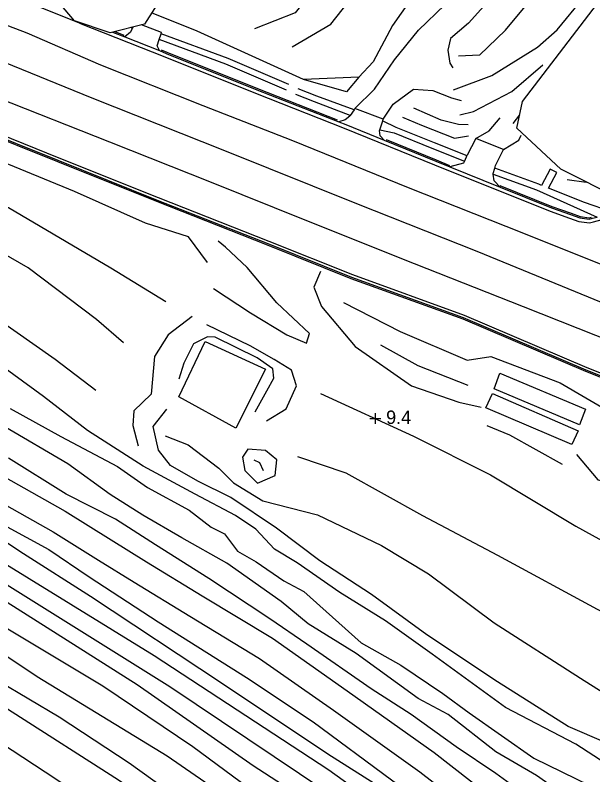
# Model space of a CAD drawing. Extents: x 2316231 to 2323598, y 363169 to 371906.
# Drawn here: x 2320501.8 to 2320716.5, y 365899 to 366181.3 of the extents above; entities that cross this region are included whole.
import ezdxf

# ---------------------------------------------------------------- set-up
doc = ezdxf.new("R2010")
doc.units = 0
for name, color, linetype in [('RD_DTM_BkLn1', 7, 'Continuous'), ('RD_DTM_Holes', 7, 'Continuous'), ('RD_DTM_Void', 7, 'Continuous'), ('RD_EX_H2O', 7, 'Continuous'), ('RD_EX_Road', 7, 'Continuous')]:
    doc.layers.add(name, color=color, linetype=linetype)

msp = doc.modelspace()

# ---------------------------------------------------------------- linework, layer by layer
at = {"layer": 'RD_DTM_BkLn1'}
for p, q in [((2320629.575, 366158.256), (2320608.931, 366157.378)), ((2320689.326, 366144.194), (2320686.807, 366141.06)), ((2320706.982, 366120.247), (2320714.138, 366119.274))]:
    msp.add_line(p, q, dxfattribs=at)
for points in [[(2320533.6, 366162.638), (2320506.3, 366174.535), (2320465.853, 366190.084), (2320436.355, 366201.486), (2320415.415, 366210.263), (2320393.459, 366218.872), (2320360.843, 366231.403), (2320327.669, 366244.242), (2320294.269, 366258.238), (2320257.317, 366273.156), (2320231.348, 366282.823)], [(2320577.045, 366272.997), (2320581.683, 366268.882), (2320590.588, 366269.346), (2320603.735, 366274.18), (2320622.56, 366276.839), (2320630.763, 366265.105), (2320644.145, 366234.528), (2320652.277, 366208.945), (2320650.853, 366190.101), (2320642.133, 366177.456), (2320634.842, 366163.914), (2320629.575, 366158.256)], [(2320519.241, 366194.477), (2320517.839, 366195.025), (2320508.812, 366198.914), (2320511.466, 366211.647), (2320513.766, 366225.597), (2320524.093, 366232.701), (2320536.386, 366233.795), (2320560.592, 366247.081), (2320573.262, 366252.151), (2320604.622, 366257.303), (2320620.601, 366248.036), (2320623.573, 366223.725), (2320619.71, 366199.683), (2320605.893, 366182.184), (2320590.826, 366176.244)], [(2320684.118, 366175.719), (2320698.663, 366193.461), (2320705.301, 366220.646), (2320700.697, 366236.714)], [(2320703.263, 366175.789), (2320713.115, 366187.867), (2320715.921, 366209.139), (2320713.631, 366228.767)], [(2320604.733, 366169.498), (2320619.153, 366177.986), (2320629.474, 366191.076), (2320638.22, 366215.983)], [(2320670.36, 366178.243), (2320687.373, 366197.435), (2320689.378, 366210.814), (2320686.67, 366215.628)], [(2320608.931, 366157.378), (2320569.481, 366175.328), (2320552.531, 366182.119)], [(2320664.793, 366153.588), (2320679.052, 366158.907), (2320695.928, 366169.428), (2320703.263, 366175.789)], [(2320684.118, 366175.719), (2320674.371, 366166.422), (2320666.555, 366166.07)], [(2321058.006, 365893.08), (2321033.886, 365912.075), (2321009.778, 365931.141), (2320983.8, 365949.981), (2320952.381, 365971.253), (2320929.192, 365985.285), (2320903.037, 365999.401), (2320870.781, 366015.093), (2320839.103, 366027.859), (2320803.486, 366042.258), (2320766.516, 366057.135), (2320724.624, 366072.486), (2320673.583, 366093.446), (2320628.837, 366111.148), (2320579.72, 366130.879), (2320530.352, 366150.424), (2320494.149, 366165.157)], [(2321069.926, 365902.304), (2321045.935, 365921.214), (2321024.91, 365937.287), (2321006.228, 365951.677), (2320983.871, 365968.062), (2320962.43, 365982.06), (2320941.958, 365993.151), (2320911.963, 366009.193), (2320883.216, 366022.963), (2320847.464, 366037.895), (2320813.645, 366051.48), (2320761.655, 366072.109), (2320728.302, 366085.144), (2320690.226, 366100.377), (2320648.068, 366117.161), (2320605.031, 366134.547), (2320571.655, 366147.595), (2320533.6, 366162.638)], [(2320667.112, 366144.247), (2320672.185, 366145.508), (2320686.411, 366152.954), (2320697.926, 366162.797)], [(2320573.321, 366089.418), (2320566.172, 366098.949), (2320550.209, 366103.969), (2320523.872, 366115.782), (2320485.436, 366131.516), (2320459.833, 366142.458), (2320423.52, 366157.007)], [(2320629.575, 366158.256), (2320624.981, 366152.783), (2320608.931, 366157.378)], [(2320557.741, 366074.745), (2320537.357, 366087.276), (2320499.275, 366109.706), (2320450.502, 366132.41), (2320411.79, 366155.498)], [(2320531.807, 366041.883), (2320516.681, 366053.392), (2320478.743, 366079.814), (2320453.669, 366097.202), (2320427.237, 366118.435), (2320403.359, 366133.196), (2320387.968, 366137.594), (2320361.237, 366152.852)], [(2320183.14, 366148.693), (2320239.09, 366117.639), (2320296.494, 366085.739), (2320349.802, 366055.132), (2320405.378, 366025.418), (2320448.083, 365999.362), (2320490.768, 365974.618), (2320559.324, 365931.873), (2320617.279, 365892.959), (2320678.148, 365848.809), (2320727.47, 365811.314), (2320779.04, 365769.194), (2320836.996, 365719.869), (2320889.686, 365671.382)], [(2321107.857, 365825.845), (2321089.033, 365845.956), (2321064.914, 365868.827), (2321040.152, 365890.43), (2321013.859, 365911.449), (2320983.706, 365933.792), (2320958.395, 365951.148), (2320936.89, 365964.698), (2320914.976, 365977.721), (2320890.131, 365990.721), (2320868.682, 366001.198), (2320834.466, 366016.123), (2320800.88, 366029.386), (2320770.06, 366041.822), (2320731.461, 366056.849), (2320690.819, 366072.905), (2320650.247, 366088.926), (2320609.558, 366105.101), (2320574.835, 366119.134), (2320536.92, 366134.034), (2320494.89, 366150.627)], [(2320125.425, 366145.994), (2320161.294, 366129.015), (2320184.806, 366118.194), (2320219.268, 366097.334), (2320257.75, 366078.61), (2320301.401, 366053.593), (2320339.6, 366032.049), (2320388.854, 366006.136), (2320433.491, 365980.54), (2320471.094, 365961.437), (2320509.936, 365935.57), (2320558.33, 365906.04), (2320596.656, 365879.53), (2320637.36, 365850.344), (2320679.307, 365816.521), (2320703.841, 365798.525), (2320711.978, 365788.521), (2320716.795, 365779.622), (2320731.36, 365769.609), (2320746.226, 365761.92), (2320773.664, 365741.714), (2320802.121, 365716.946), (2320848.849, 365676.056), (2320875.469, 365654.227)], [(2320542.082, 366059.505), (2320531.991, 366068.175), (2320506.632, 366087.35), (2320470.997, 366107.883), (2320446.3, 366121.378), (2320401.38, 366146.067)], [(2320670.174, 366140.558), (2320666.583, 366140.697), (2320660.21, 366142.3), (2320649.948, 366146.765)], [(2320182.737, 366143.817), (2320231.045, 366116.001), (2320278.866, 366087.979), (2320328.405, 366059.321), (2320373.611, 366034.853), (2320417.281, 366010.392), (2320460.243, 365986.01), (2320498.805, 365963.232), (2320547.113, 365932.568), (2320590.276, 365902.488), (2320625.131, 365879.992), (2320670.35, 365847.996), (2320704.214, 365820.962), (2320721.604, 365807.145), (2320731.665, 365799.894), (2320745.055, 365790.38), (2320759.08, 365777.797), (2320794.333, 365748.347), (2320828.782, 365718.919), (2320859.537, 365690.73), (2320885.477, 365666.303)], [(2320645.769, 366143.342), (2320652.812, 366140.43), (2320665.172, 366135.574), (2320670.289, 366136.491)], [(2320232.419, 366129.527), (2320276.765, 366104.361), (2320326.97, 366076.072), (2320377.845, 366047.504), (2320438.873, 366013.35), (2320491.432, 365981.475), (2320553.439, 365943.338), (2320618.359, 365900.899), (2320682.218, 365854.928), (2320740.085, 365810.827), (2320800.745, 365760.357), (2320857.803, 365711.976), (2320894.516, 365677.21)], [(2320320.221, 366098.87), (2320343.73, 366084.834), (2320356.505, 366077.219), (2320384.555, 366059.676), (2320419.447, 366040.181), (2320447.866, 366021.901), (2320471.868, 366008.615), (2320488.936, 365996.515), (2320514.303, 365982.74), (2320529.316, 365972.626), (2320554.954, 365955.917), (2320587.739, 365935.149), (2320612.576, 365918.662), (2320641.664, 365897.147), (2320678.381, 365870.456), (2320716.77, 365840.459), (2320734.571, 365828.326), (2320756.632, 365810.066), (2320790.938, 365779.493), (2320809.818, 365763.92), (2320848.173, 365729.232), (2320863.138, 365716.2), (2320899.36, 365685.757), (2320900.62, 365684.576)], [(2320315.308, 366088.614), (2320345.863, 366070.993), (2320387.782, 366047.357), (2320430.265, 366024.388), (2320470.415, 366003.883), (2320504.878, 365981.214), (2320529.854, 365965.458), (2320578.485, 365933.231), (2320618.03, 365906.824), (2320639.032, 365893.635), (2320675.308, 365866.642), (2320706.175, 365841.844), (2320753.882, 365805.574), (2320792.936, 365773.891), (2320828.235, 365743.377), (2320879.989, 365695.168), (2320896.418, 365679.505)], [(2320623.799, 366074.563), (2320644.902, 366063.772), (2320669.823, 366053.098), (2320678.655, 366054.407), (2320704.426, 366044.656), (2320723.457, 366033.572), (2320735.647, 366023.576), (2320753.929, 366012.205), (2320762.157, 366006.679), (2320763.27, 365997.376), (2320762.504, 365991.761), (2320773.429, 365985.539)], [(2320567.611, 366069.257), (2320558.724, 366062.537), (2320553.578, 366054.494), (2320552.293, 366040.517), (2320545.965, 366034.321), (2320545.565, 366028.76), (2320547.505, 366021.302)], [(2320591.032, 366033.915), (2320595.371, 366041.673), (2320597.971, 366046.403), (2320597.553, 366049.906), (2320591.766, 366053.949), (2320576.132, 366061.623), (2320573.332, 366061.753), (2320568.077, 366059.218), (2320564.537, 366051.982), (2320562.691, 366046.061)], [(2320768.392, 365866.361), (2320756.708, 365877.083), (2320744.252, 365887.566), (2320740.687, 365890.766), (2320726.055, 365900.142), (2320710.288, 365910.418), (2320684.057, 365924.05), (2320656.815, 365943.875), (2320639.525, 365956.203), (2320622.508, 365966.719), (2320606.645, 365977.824), (2320598.246, 365982.88), (2320591.282, 365990.258), (2320583.747, 365995.374), (2320568.719, 366003.277), (2320549.326, 366013.752), (2320528.668, 366027.008), (2320512.279, 366039.596), (2320486.864, 366058.051)], [(2320670.261, 366043.662), (2320651.645, 366051.043), (2320637.676, 366058.638)], [(2320615.366, 366040.68), (2320649.844, 366024.913), (2320678.476, 366010.483), (2320710.266, 365991.463), (2320738.082, 365976.027), (2320772.798, 365958.579), (2320790.365, 365945.728)], [(2320499.898, 366035.117), (2320518.783, 366024.708), (2320539.775, 366013.575), (2320551, 366005.825), (2320566.423, 365997.349), (2320574.595, 365991.103), (2320579.668, 365988.57), (2320584.457, 365982.129), (2320591.38, 365978.131), (2320601.704, 365971.102), (2320609.064, 365967.122), (2320630.418, 365948.02), (2320645.146, 365939.719), (2320660.769, 365929.255), (2320670.56, 365922.043), (2320694.612, 365905.223), (2320715.486, 365895.037), (2320733.213, 365880.79), (2320746.065, 365874.627), (2320761.94, 365859.741), (2320768.707, 365850.734), (2320770.054, 365844.1)], [(2320764.035, 365845.663), (2320752.506, 365853.724), (2320736.562, 365865.941), (2320722.342, 365878.987), (2320705.589, 365891.721), (2320695.572, 365898.724), (2320680.484, 365907.597), (2320662.741, 365921.455), (2320651.647, 365927.407), (2320628.585, 365944.084), (2320610.724, 365955.154), (2320600.628, 365963.434), (2320580.454, 365977.629), (2320563.696, 365987.078), (2320549.277, 365995.494), (2320537.141, 366003.22), (2320521.388, 366014.595), (2320497.7, 366028.456)], [(2320677.167, 366028.804), (2320685.55, 366025.332), (2320705.186, 366014.441)], [(2320557.596, 366025.006), (2320566.158, 366021.65), (2320577.537, 366013.023), (2320583, 366007.52), (2320593.883, 366000.802), (2320614.146, 365995.646), (2320637.946, 365984.183), (2320655.496, 365973.743), (2320679.838, 365955.502), (2320712.01, 365934.894), (2320739.613, 365917.475), (2320762.81, 365900.264)], [(2320778.851, 365827.229), (2320776.707, 365828.796), (2320760.961, 365838.918), (2320748.976, 365847.328), (2320737.491, 365856.96), (2320731.391, 365861.609), (2320718.843, 365870.309), (2320708.251, 365878.642), (2320699.269, 365885.241), (2320691.419, 365891.649), (2320680.432, 365899.55), (2320665.759, 365909.434), (2320648.973, 365921.401), (2320634.153, 365930.933), (2320610.18, 365947.515), (2320596.411, 365956.939), (2320573.742, 365971.933), (2320553.973, 365984.422), (2320539.048, 365994.014), (2320520.799, 366003.328), (2320499.315, 366016.701)], [(2320590.504, 366016.077), (2320592.571, 366015.035), (2320594.047, 366012.121)], [(2320606.697, 366017.247), (2320624.739, 366011.232), (2320653.282, 365995.385), (2320681.071, 365980.599), (2320718.12, 365960.616), (2320755.163, 365941.178), (2320778.753, 365919.388)], [(2320543.695, 365879.161), (2320517.247, 365897.216), (2320496.287, 365910.936), (2320471.832, 365924.913)]]:
    msp.add_lwpolyline(points, dxfattribs=at)
at = {"layer": 'RD_DTM_Holes'}
for points in [[(2320743.184, 366208.848), (2320746.914, 366221.959), (2320763.81, 366237.757), (2320780.684, 366241.725), (2320800.176, 366254.868), (2320811.003, 366246.359), (2320800.733, 366223.679), (2320777.231, 366171.911), (2320759.986, 366170.011), (2320738.35, 366162.342), (2320738.441, 366149.94), (2320744.083, 366125.412), (2320726.638, 366113.037), (2320704.663, 366124.002), (2320688.271, 366139.316), (2320690.415, 366149.23), (2320722.742, 366191.581), (2320740.581, 366196.767), (2320743.184, 366208.848)], [(2320516.901, 366187.518), (2320522.26, 366203.453), (2320535.193, 366209.525), (2320546.861, 366206.283), (2320557.353, 366189.738), (2320549.875, 366177.924), (2320537.102, 366174.768), (2320523.785, 366179.153), (2320516.901, 366187.518)]]:
    msp.add_lwpolyline(points, dxfattribs=at)
at = {"layer": 'RD_DTM_Void'}
for p, q in [((2320635.704, 366029.379), (2320635.704, 366033.379)), ((2320633.704, 366031.379), (2320637.704, 366031.379))]:
    msp.add_line(p, q, dxfattribs=at)
at = {"layer": 'RD_EX_H2O'}
msp.add_lwpolyline([(2320221.567, 366109.612), (2320246.01, 366095.432), (2320275.628, 366082.36), (2320308.416, 366062.762), (2320348.828, 366042.465), (2320390.844, 366019.006), (2320428.93, 365996.954), (2320463.386, 365976.566), (2320497.874, 365954.051), (2320534.331, 365932.126), (2320567.896, 365909.551), (2320591.597, 365891.98), (2320624.103, 365868.768), (2320651.363, 365847.548), (2320681.527, 365825.11), (2320715.721, 365799.88), (2320721.819, 365795.078), (2320726.404, 365790.317)], dxfattribs=at)
at = {"layer": 'RD_EX_Road'}
for p, q in [((2320545.345, 366176.462), (2320544.827, 366176.677)), ((2320545.51, 366176.845), (2320545.345, 366176.462)), ((2320537.941, 366174.975), (2320542.521, 366173.17)), ((2320538.779, 366175.182), (2320542.179, 366173.843)), ((2320555.346, 366172.242), (2320556.058, 366174.386)), ((2320542.521, 366173.17), (2320555.402, 366168.094)), ((2320627.798, 366146.159), (2320626.335, 366143.959)), ((2320628.059, 366146.552), (2320627.798, 366146.159)), ((2320638.659, 366142.686), (2320628.059, 366146.552)), ((2320638.425, 366141.988), (2320638.659, 366142.686)), ((2320637.305, 366138.645), (2320638.425, 366141.988)), ((2320683.378, 366131.341), (2320673.077, 366135.475)), ((2320669.761, 366129.124), (2320668.807, 366127.074)), ((2320663.405, 366124.902), (2320682.132, 366117.369))]:
    msp.add_line(p, q, dxfattribs=at)
for points in [[(2320525.687, 366178.3), (2320494.71, 366190.867), (2320471.263, 366199.836), (2320462.353, 366203.747), (2320458.995, 366207.468), (2320457.102, 366212.124), (2320456.848, 366216.034), (2320457.384, 366219.286), (2320459.24, 366222.866), (2320461.065, 366225.316), (2320463.983, 366227.116)], [(2320642.868, 366164.721), (2320651.734, 366175.663), (2320661.587, 366185.128), (2320669.911, 366189.341)], [(2320525.687, 366178.3), (2320557.451, 366165.781), (2320591.141, 366152.281), (2320624.153, 366139.344), (2320657.628, 366125.717), (2320700.643, 366108.414), (2320707.82, 366105.89), (2320711.349, 366104.617), (2320715.278, 366104.084), (2320716.819, 366104.455), (2320721.941, 366105.833), (2320725.997, 366107.922), (2320741.619, 366117.359)], [(2320545.345, 366176.462), (2320545.182, 366176.085), (2320544.672, 366174.968), (2320542.521, 366173.17)], [(2320556.058, 366174.386), (2320556.192, 366174.79), (2320548.751, 366177.646)], [(2320670.36, 366178.243), (2320663.649, 366172.642), (2320662.603, 366168.227), (2320663.399, 366163.473), (2320664.542, 366161.681)], [(2320603.582, 366155.511), (2320580.964, 366165.149), (2320556.058, 366174.386)], [(2320555.402, 366168.094), (2320554.547, 366169.835), (2320555.346, 366172.242)], [(2320602.697, 366153.433), (2320580.128, 366163.051), (2320555.346, 366172.242)], [(2320555.402, 366168.094), (2320557.968, 366167.082), (2320591.657, 366153.582), (2320622.1, 366141.652)], [(2320556.123, 366168.347), (2320558.153, 366167.547), (2320591.841, 366154.047), (2320621.479, 366142.433)], [(2320628.059, 366146.552), (2320635.322, 366153.765), (2320642.868, 366164.721)], [(2320447.49, 366154.754), (2320486.483, 366139.322), (2320517.512, 366126.884), (2320554.37, 366112.125), (2320595.484, 366095.957), (2320626.618, 366083.485), (2320668.202, 366068.427), (2320713.793, 366048.997), (2320754.649, 366032.79), (2320790.78, 366018.264), (2320827.322, 366004.261), (2320859.859, 365990.434), (2320860.606, 365990.068)], [(2320447.674, 366155.219), (2320486.668, 366139.786), (2320517.698, 366127.348), (2320554.555, 366112.59), (2320595.668, 366096.421), (2320626.796, 366083.952), (2320668.386, 366068.892), (2320713.983, 366049.459), (2320754.834, 366033.255), (2320790.963, 366018.729), (2320827.509, 366004.724), (2320860.067, 365990.889), (2320885.094, 365978.649), (2320911.633, 365964.468), (2320938.685, 365948.462), (2320963.813, 365931.227), (2320989.061, 365912.998), (2320994.251, 365909.193)], [(2320448.042, 366156.149), (2320487.038, 366140.715), (2320518.07, 366128.276), (2320554.923, 366113.519), (2320596.037, 366097.351), (2320627.152, 366084.887), (2320668.752, 366069.823), (2320714.363, 366050.384), (2320755.205, 366034.183), (2320791.329, 366019.66), (2320827.884, 366005.652), (2320860.482, 365991.798), (2320885.549, 365979.54), (2320912.128, 365965.36), (2320939.252, 365949.341), (2320964.386, 365932.047), (2320989.736, 365914.065), (2321018.031, 365893.376), (2321045.482, 365870.404), (2321073.271, 365845.183), (2321101.868, 365815.556), (2321105.507, 365811.232)], [(2320627.798, 366146.159), (2320613.955, 366151.211), (2320606.96, 366153.877)], [(2320638.659, 366142.686), (2320642.285, 366148.219), (2320649.916, 366153.726), (2320657.049, 366153.342), (2320663.952, 366150.55), (2320667.627, 366149.571)], [(2320626.335, 366143.959), (2320613.134, 366149.107), (2320606.156, 366151.767)], [(2320626.335, 366143.959), (2320626.181, 366143.727), (2320624.463, 366142.437), (2320622.1, 366141.652)], [(2320673.077, 366135.475), (2320678.016, 366138.274), (2320682.094, 366143.116)], [(2320622.1, 366141.652), (2320624.672, 366140.645), (2320638.96, 366134.828)], [(2320638.425, 366141.988), (2320643.289, 366139.662), (2320657.535, 366134.016), (2320669.761, 366129.124)], [(2320638.96, 366134.828), (2320637.541, 366136.437), (2320637.235, 366138.437), (2320637.305, 366138.645)], [(2320637.305, 366138.645), (2320642.732, 366137.566), (2320656.696, 366131.919), (2320668.807, 366127.074)], [(2320683.378, 366131.341), (2320688.999, 366134.852), (2320689.92, 366136.673)], [(2320638.96, 366134.828), (2320658.154, 366127.015), (2320663.405, 366124.902)], [(2320639.707, 366135.064), (2320658.341, 366127.478), (2320663.309, 366125.48)], [(2320673.077, 366135.475), (2320669.821, 366129.253), (2320669.761, 366129.124)], [(2320680.137, 366124.436), (2320680.42, 366125.375), (2320683.378, 366131.341)], [(2320668.807, 366127.074), (2320668.449, 366126.303), (2320663.405, 366124.902)], [(2320679.537, 366122.25), (2320679.521, 366122.396), (2320680.137, 366124.436)], [(2320723.518, 366108.219), (2320713.396, 366111.715), (2320700.037, 366117.02), (2320703.136, 366122.84), (2320700.745, 366124.113), (2320697.504, 366118.026), (2320696.442, 366118.448), (2320680.137, 366124.436)], [(2320682.132, 366117.369), (2320679.819, 366119.757), (2320679.537, 366122.25)], [(2320679.537, 366122.25), (2320695.636, 366116.338), (2320718.149, 366106.262)], [(2320681.988, 366117.966), (2320701.313, 366110.192), (2320708.457, 366107.68), (2320711.805, 366106.473), (2320715.18, 366106.015), (2320716.002, 366106.213)], [(2320682.132, 366117.369), (2320701.136, 366109.724), (2320708.29, 366107.209), (2320711.685, 366105.985), (2320715.206, 366105.507), (2320716.473, 366105.812), (2320718.149, 366106.262)], [(2320323.899, 366113.021), (2320353.981, 366094.621), (2320381.93, 366078.827), (2320411.483, 366061.572), (2320429.335, 366050.162), (2320458.032, 366033.49), (2320473.353, 366024.244), (2320495.209, 366011.149), (2320520.435, 365996.933), (2320537.434, 365986.383), (2320550.651, 365978.213), (2320571.299, 365965.571), (2320597.468, 365949.743), (2320625.215, 365930.292), (2320657.566, 365907.315), (2320685.711, 365885.437), (2320710.189, 365868.145), (2320725.44, 365856.384), (2320753.441, 365840.046), (2320767.348, 365829.779), (2320786.407, 365812.075), (2320806.036, 365794.449), (2320821.311, 365780.953), (2320846.032, 365756.88)], [(2320319.14, 366105.537), (2320349.484, 366086.977), (2320377.513, 366071.138), (2320406.858, 366054.005), (2320424.718, 366042.589), (2320453.513, 366025.86), (2320468.783, 366016.645), (2320490.753, 366003.481), (2320515.919, 365989.3), (2320532.765, 365978.844), (2320546.005, 365970.66), (2320566.689, 365957.996), (2320592.623, 365942.31), (2320620.103, 365923.046), (2320652.275, 365900.197), (2320680.429, 365878.312), (2320704.921, 365861.009), (2320720.478, 365849.013), (2320748.559, 365832.628), (2320761.68, 365822.942), (2320780.427, 365805.528), (2320800.138, 365787.827), (2320815.279, 365774.45), (2320839.973, 365750.403)], [(2320575.492, 366079.749), (2320589.302, 366070.726), (2320602.814, 366062.558), (2320610.161, 366059.394), (2320611.175, 366063.033), (2320599.085, 366074.41), (2320588.045, 366087.535), (2320579.997, 366095.127), (2320577.235, 366097.336)], [(2320615.278, 366086.039), (2320612.842, 366080.207), (2320615.684, 366073.046), (2320628.251, 366058.224), (2320649.117, 366043.607), (2320666.767, 366037.479), (2320675.029, 366035.651)], [(2320595.22, 366030.532), (2320602.484, 366035.004), (2320606.349, 366043.606), (2320604.471, 366049.385), (2320598.08, 366053.399), (2320589.148, 366058.379), (2320573.032, 366066.249)], [(2320572.471, 366060.075), (2320594.843, 366049.693), (2320583.853, 366027.849), (2320562.608, 366039.493), (2320572.471, 366060.075)], [(2320681.992, 366048.269), (2320713.887, 366034.838), (2320711.558, 366029.029), (2320679.911, 366042.457), (2320681.992, 366048.269)], [(2320679.204, 366040.681), (2320711.129, 366026.884), (2320708.796, 366021.725), (2320676.798, 366035.369), (2320679.204, 366040.681)], [(2320749.542, 365895.964), (2320735.672, 365904.81), (2320707.343, 365917.038), (2320681.053, 365933.543), (2320654.823, 365951.087), (2320634.28, 365966.043), (2320615.007, 365978.502), (2320598.896, 365990.614), (2320581.914, 366002.051), (2320569.758, 366008.111), (2320559.572, 366013.898), (2320555.117, 366019.638), (2320553.135, 366028.466), (2320558.191, 366034.939)], [(2320588.317, 366019.984), (2320586.272, 366017.1), (2320587.12, 366012.043), (2320591.908, 366007.422), (2320598.49, 366010.272), (2320599.093, 366016.031), (2320594.917, 366019.498), (2320588.317, 366019.984)], [(2320710.535, 366018.028), (2320718.466, 366008.617), (2320736.006, 366005.043), (2320751.747, 365992.687), (2320755.595, 365985.596), (2320770.679, 365977.432), (2320799.112, 365976.429), (2320803.94, 365964.634), (2320800.632, 365942.789), (2320786.071, 365924.546), (2320777.359, 365906.278), (2320776.546, 365894.104)], [(2320416.682, 365973.734), (2320444.212, 365959.893), (2320470.233, 365946.476), (2320495.474, 365933.979), (2320518.139, 365920.533), (2320544.115, 365903.453), (2320574.558, 365881.626), (2320596.127, 365862.734), (2320616.537, 365844.377)], [(2320416.682, 365973.734), (2320422.387, 365970.576), (2320458.77, 365949.337), (2320500.672, 365922.44), (2320540.243, 365897.179), (2320574.201, 365873.831), (2320615.174, 365845.386), (2320616.537, 365844.377)]]:
    msp.add_lwpolyline(points, dxfattribs=at)

# ---------------------------------------------------------------- texts
at = {"layer": 'RD_DTM_Void'}
msp.add_text('9.4', height=5, dxfattribs=at).set_placement((2320639.704, 366029.379))

doc.saveas('drawing.dxf')
